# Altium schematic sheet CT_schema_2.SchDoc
size 313 x 200 mm
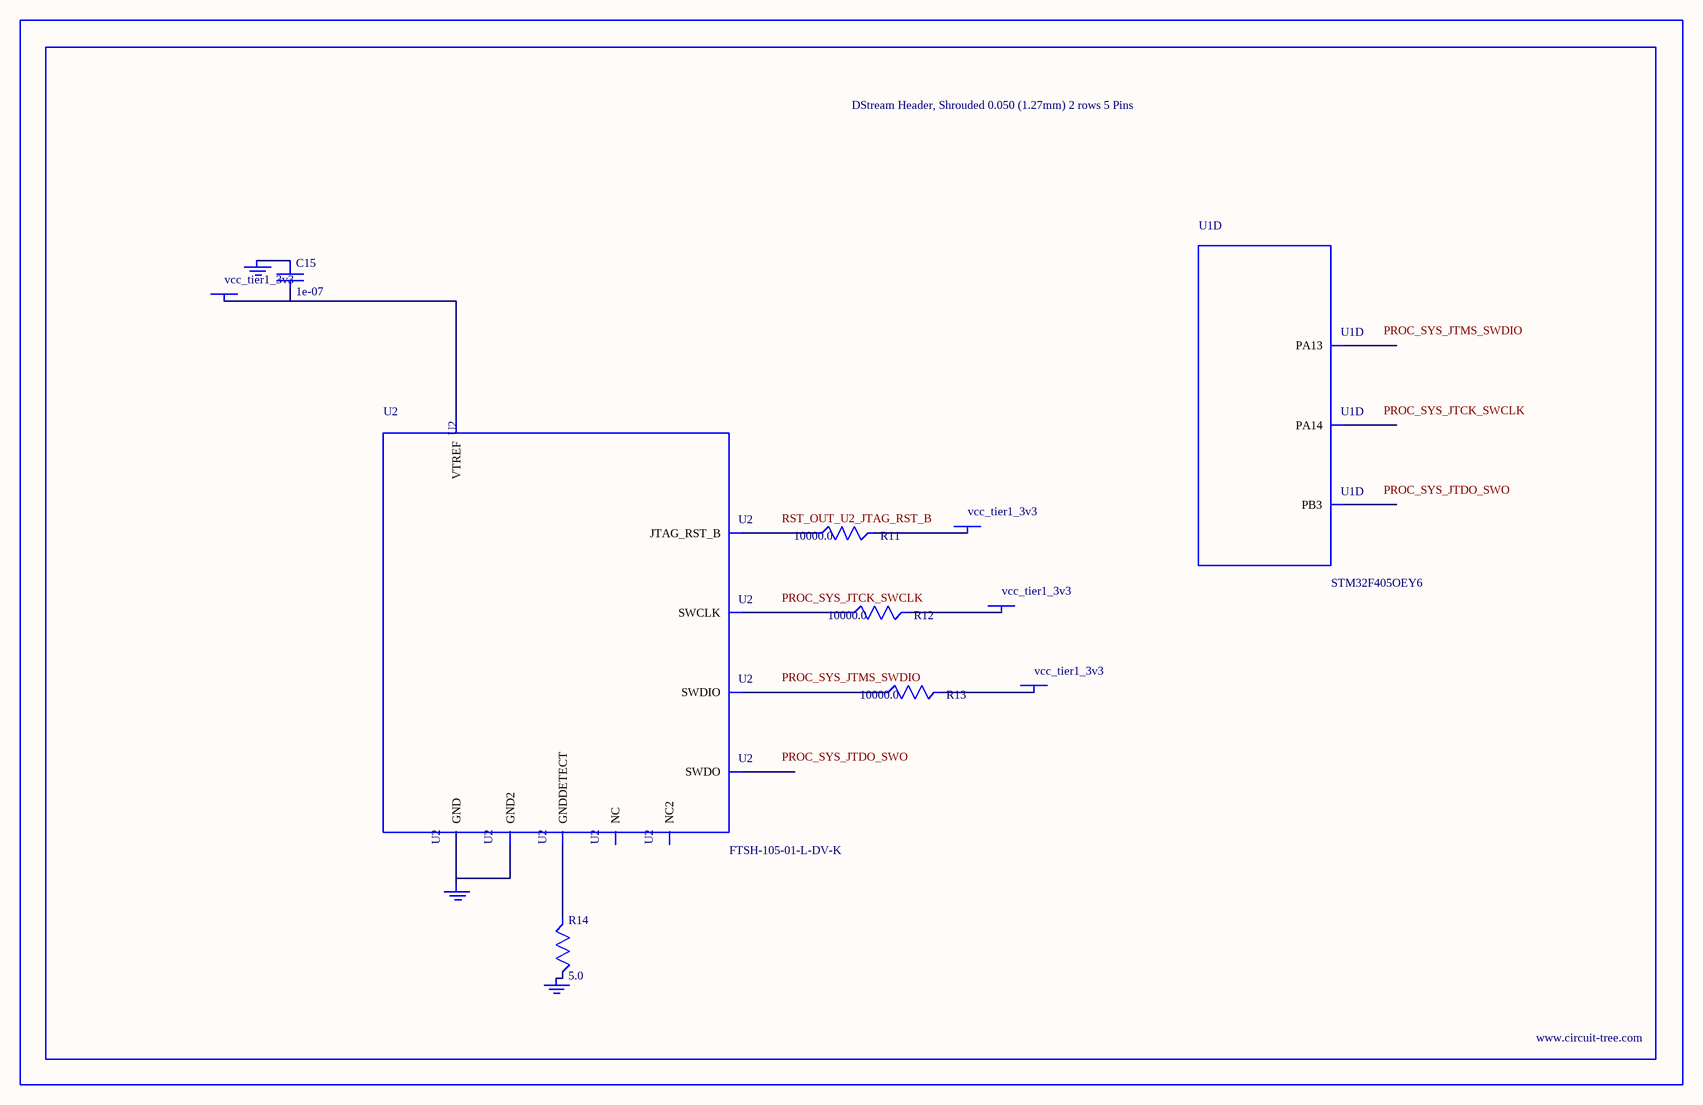
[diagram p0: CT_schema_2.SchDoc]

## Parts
BORDER1  (no value)
C15  1e-07  [C0402]
GND_INSTANCE_1_0  (no value)
GND_INSTANCE_1_1  (no value)
GND_INSTANCE_1_2  (no value)
POWER_INSTANCE_1_0  vcc_tier1_3v3
POWER_INSTANCE_1_1  vcc_tier1_3v3
POWER_INSTANCE_1_2  vcc_tier1_3v3
POWER_INSTANCE_1_3  vcc_tier1_3v3
R11  10000.0  [R0603]
R12  10000.0  [R0603]
R13  10000.0  [R0603]
R14  5.0  [R0603]
U1  STM32F405OEY6  [WLCSP90]  (part D of 8)
U2  FTSH-105-01-L-DV-K  [SAMTEC_FTSH-105-01-L-DV-K]

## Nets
NetC15_1: C15.1 GND_INSTANCE_1_0.0(GND)
NetC15_2: C15.2 POWER_INSTANCE_1_0.0(PWR) U2.1(VTREF)
NetGND_INSTANCE_1_1_0: GND_INSTANCE_1_1.0(GND) R14.2
NetGND_INSTANCE_1_2_0: GND_INSTANCE_1_2.0(GND) U2.3(GND) U2.5(GND2)
NetPOWER_INSTANCE_1_1_0: POWER_INSTANCE_1_1.0(PWR) R13.2
NetPOWER_INSTANCE_1_2_0: POWER_INSTANCE_1_2.0(PWR) R12.2
NetPOWER_INSTANCE_1_3_0: POWER_INSTANCE_1_3.0(PWR) R11.2
NetR11_1: R11.1 U2.10(JTAG_RST_B)
NetR12_1: R12.1 U2.4(SWCLK)
NetR13_1: R13.1 U2.2(SWDIO)
NetR14_1: R14.1 U2.9(GNDDETECT)

Not connected (* = marked no-connect by the designer): U1 A2(PA14) B6(PB3) D4(PA13); U2 6(SWDO) 7(NC) 8(NC2)

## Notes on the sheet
- Labels drawn without touching a wire or pin: PROC_SYS_JTCK_SWCLK, PROC_SYS_JTDO_SWO, PROC_SYS_JTMS_SWDIO, RST_OUT_U2_JTAG_RST_B

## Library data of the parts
BORDER1 = BORDER_PAGE1
C15 = C0402C104K3RACTU
GND_INSTANCE_1_0-GND_INSTANCE_1_2 = GND
POWER_INSTANCE_1_0-POWER_INSTANCE_1_3 = PWR
R11-R13 = RC0603JR-0710KL
R14 = ERJ-3GEYJ5R1V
